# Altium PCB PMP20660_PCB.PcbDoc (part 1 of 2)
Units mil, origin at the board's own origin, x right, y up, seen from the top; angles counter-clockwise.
Board outline 3850 x 3650 mil, 6 copper layers (Top Layer, MidLayer1, MidLayer2, MidLayer3, MidLayer4, Bottom Layer), stack 61.3 mil thick; 110 components, 43 nets, 1166 pads, 406 vias.
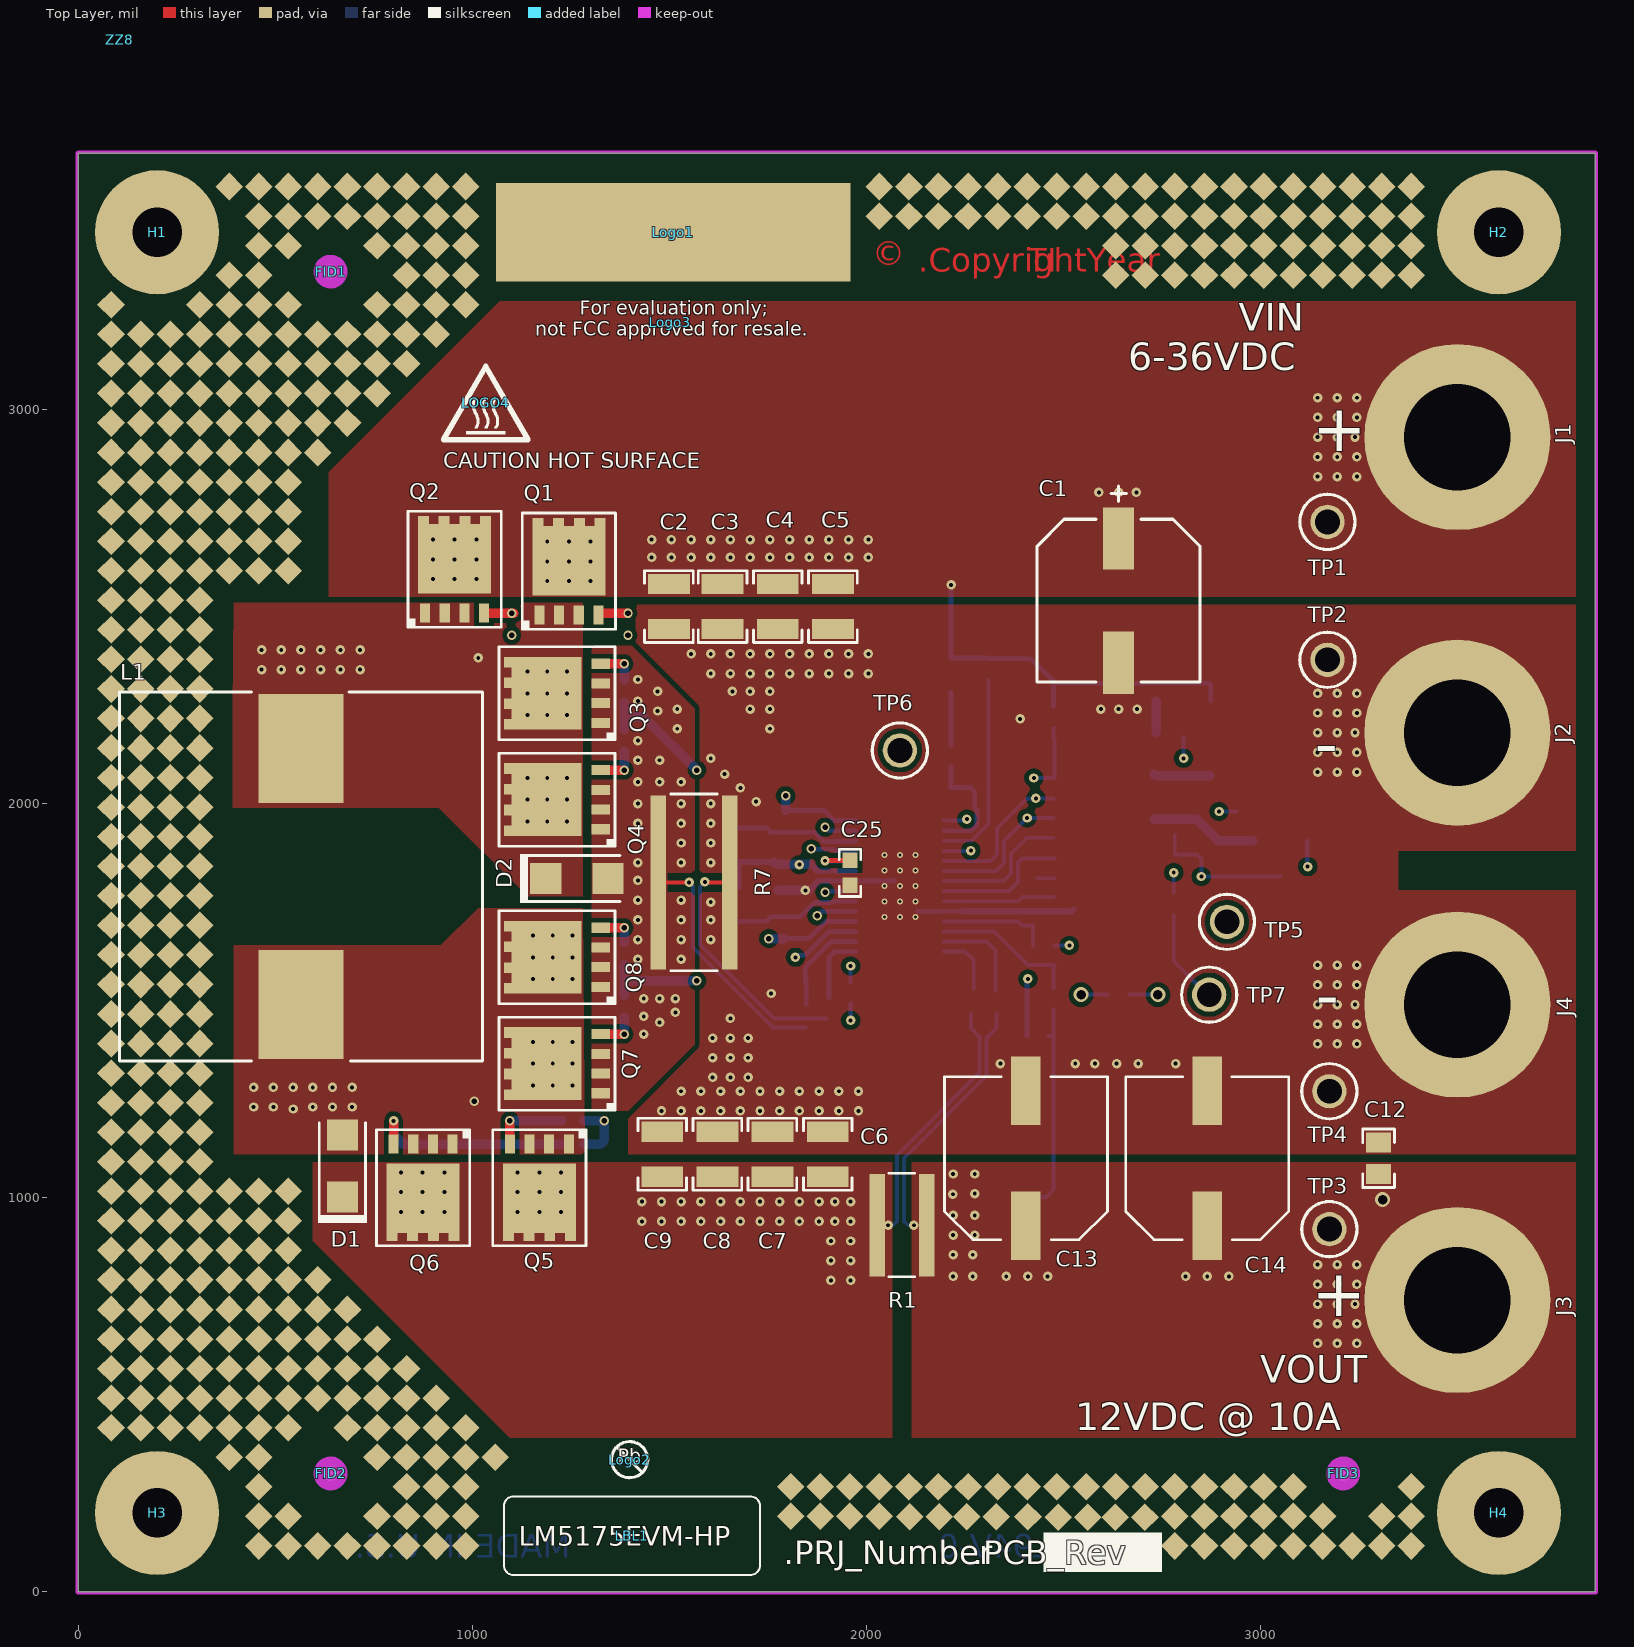
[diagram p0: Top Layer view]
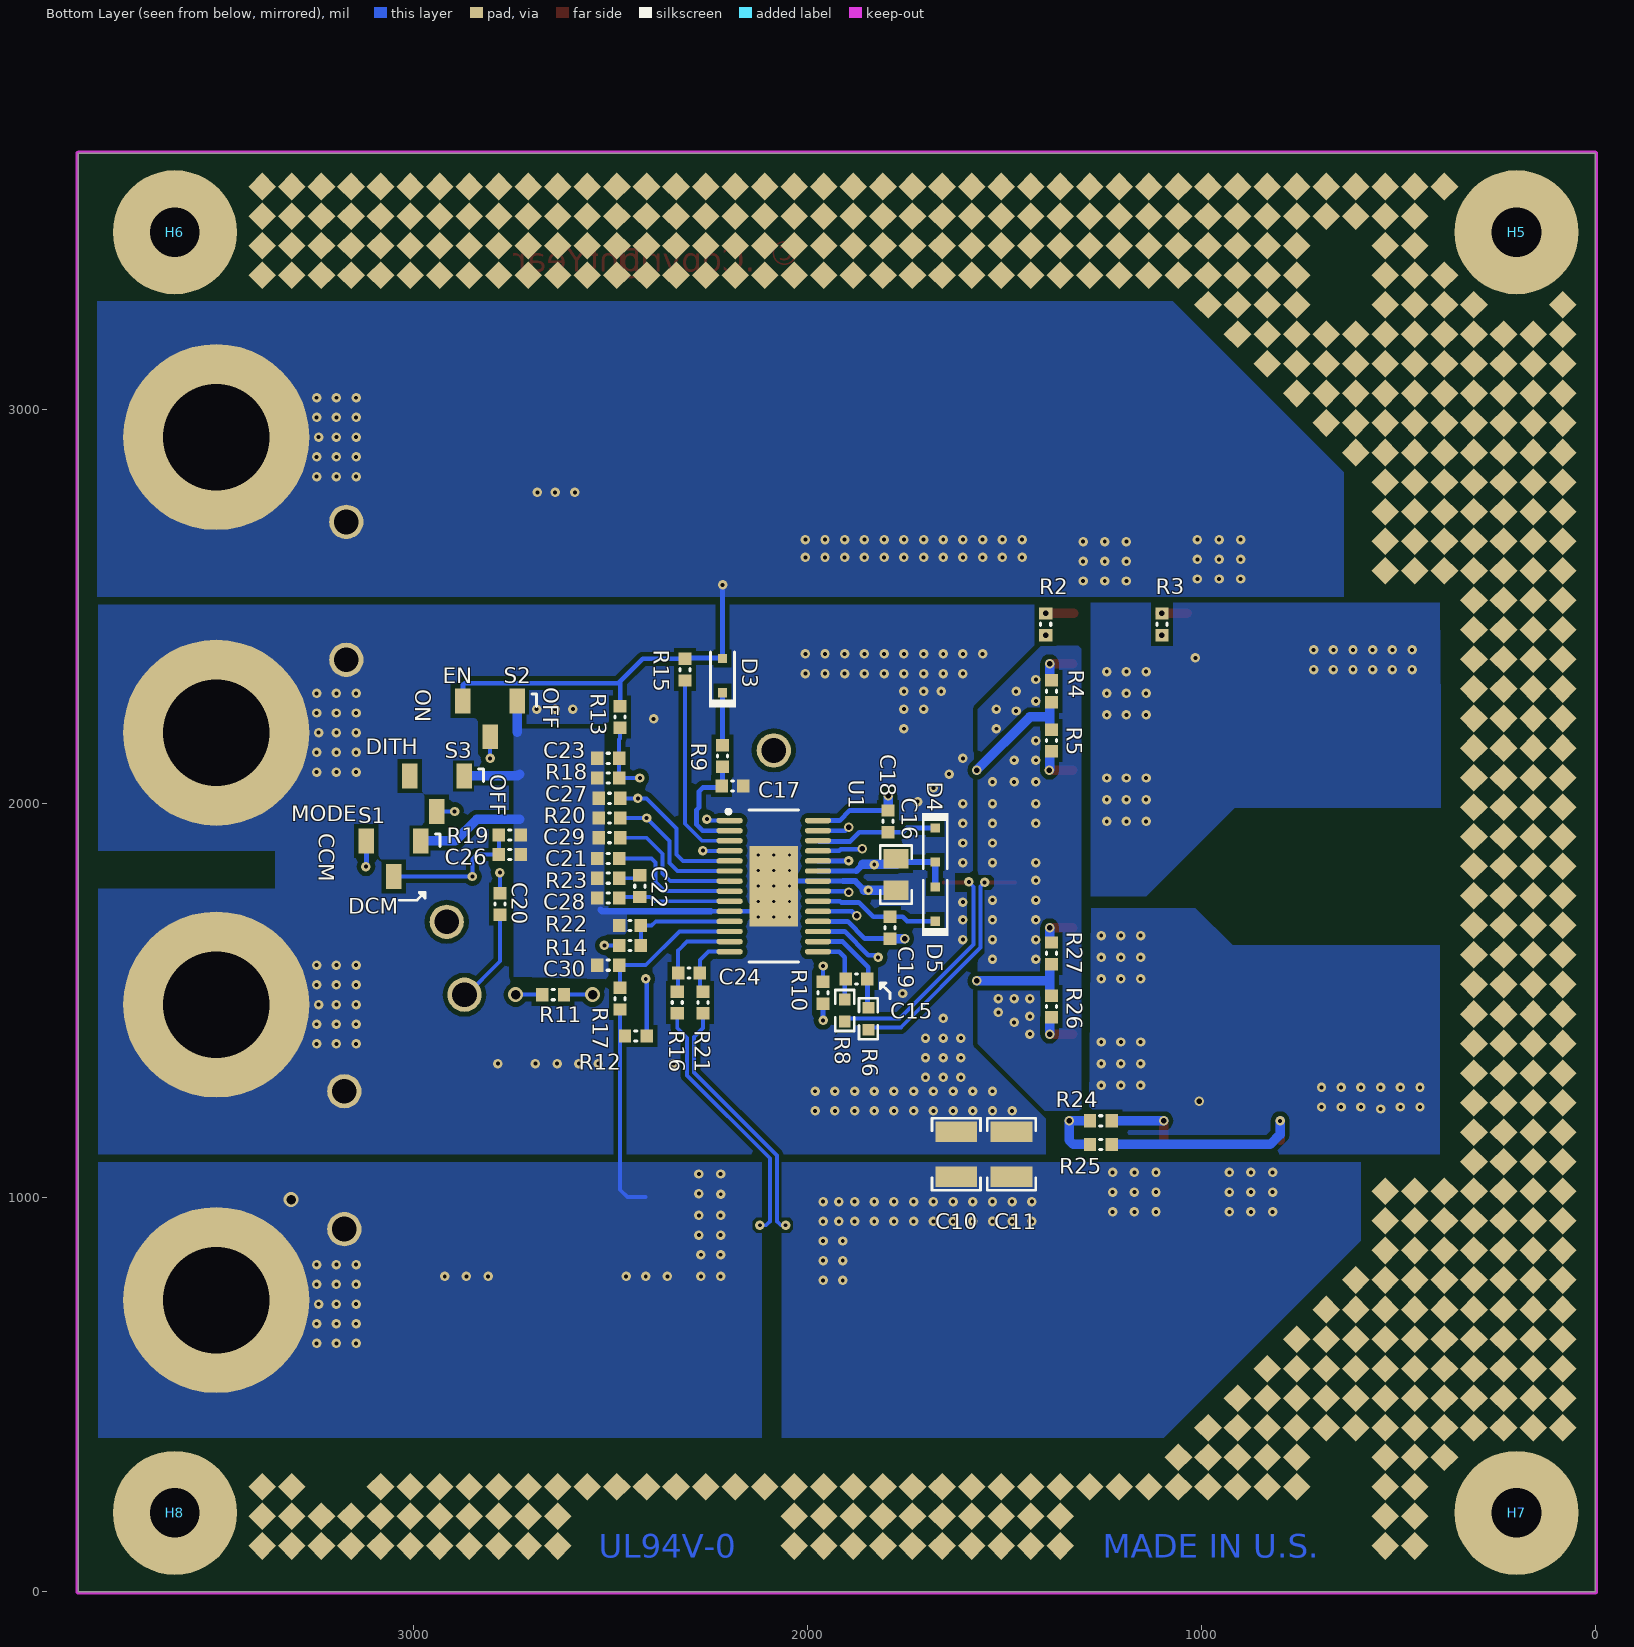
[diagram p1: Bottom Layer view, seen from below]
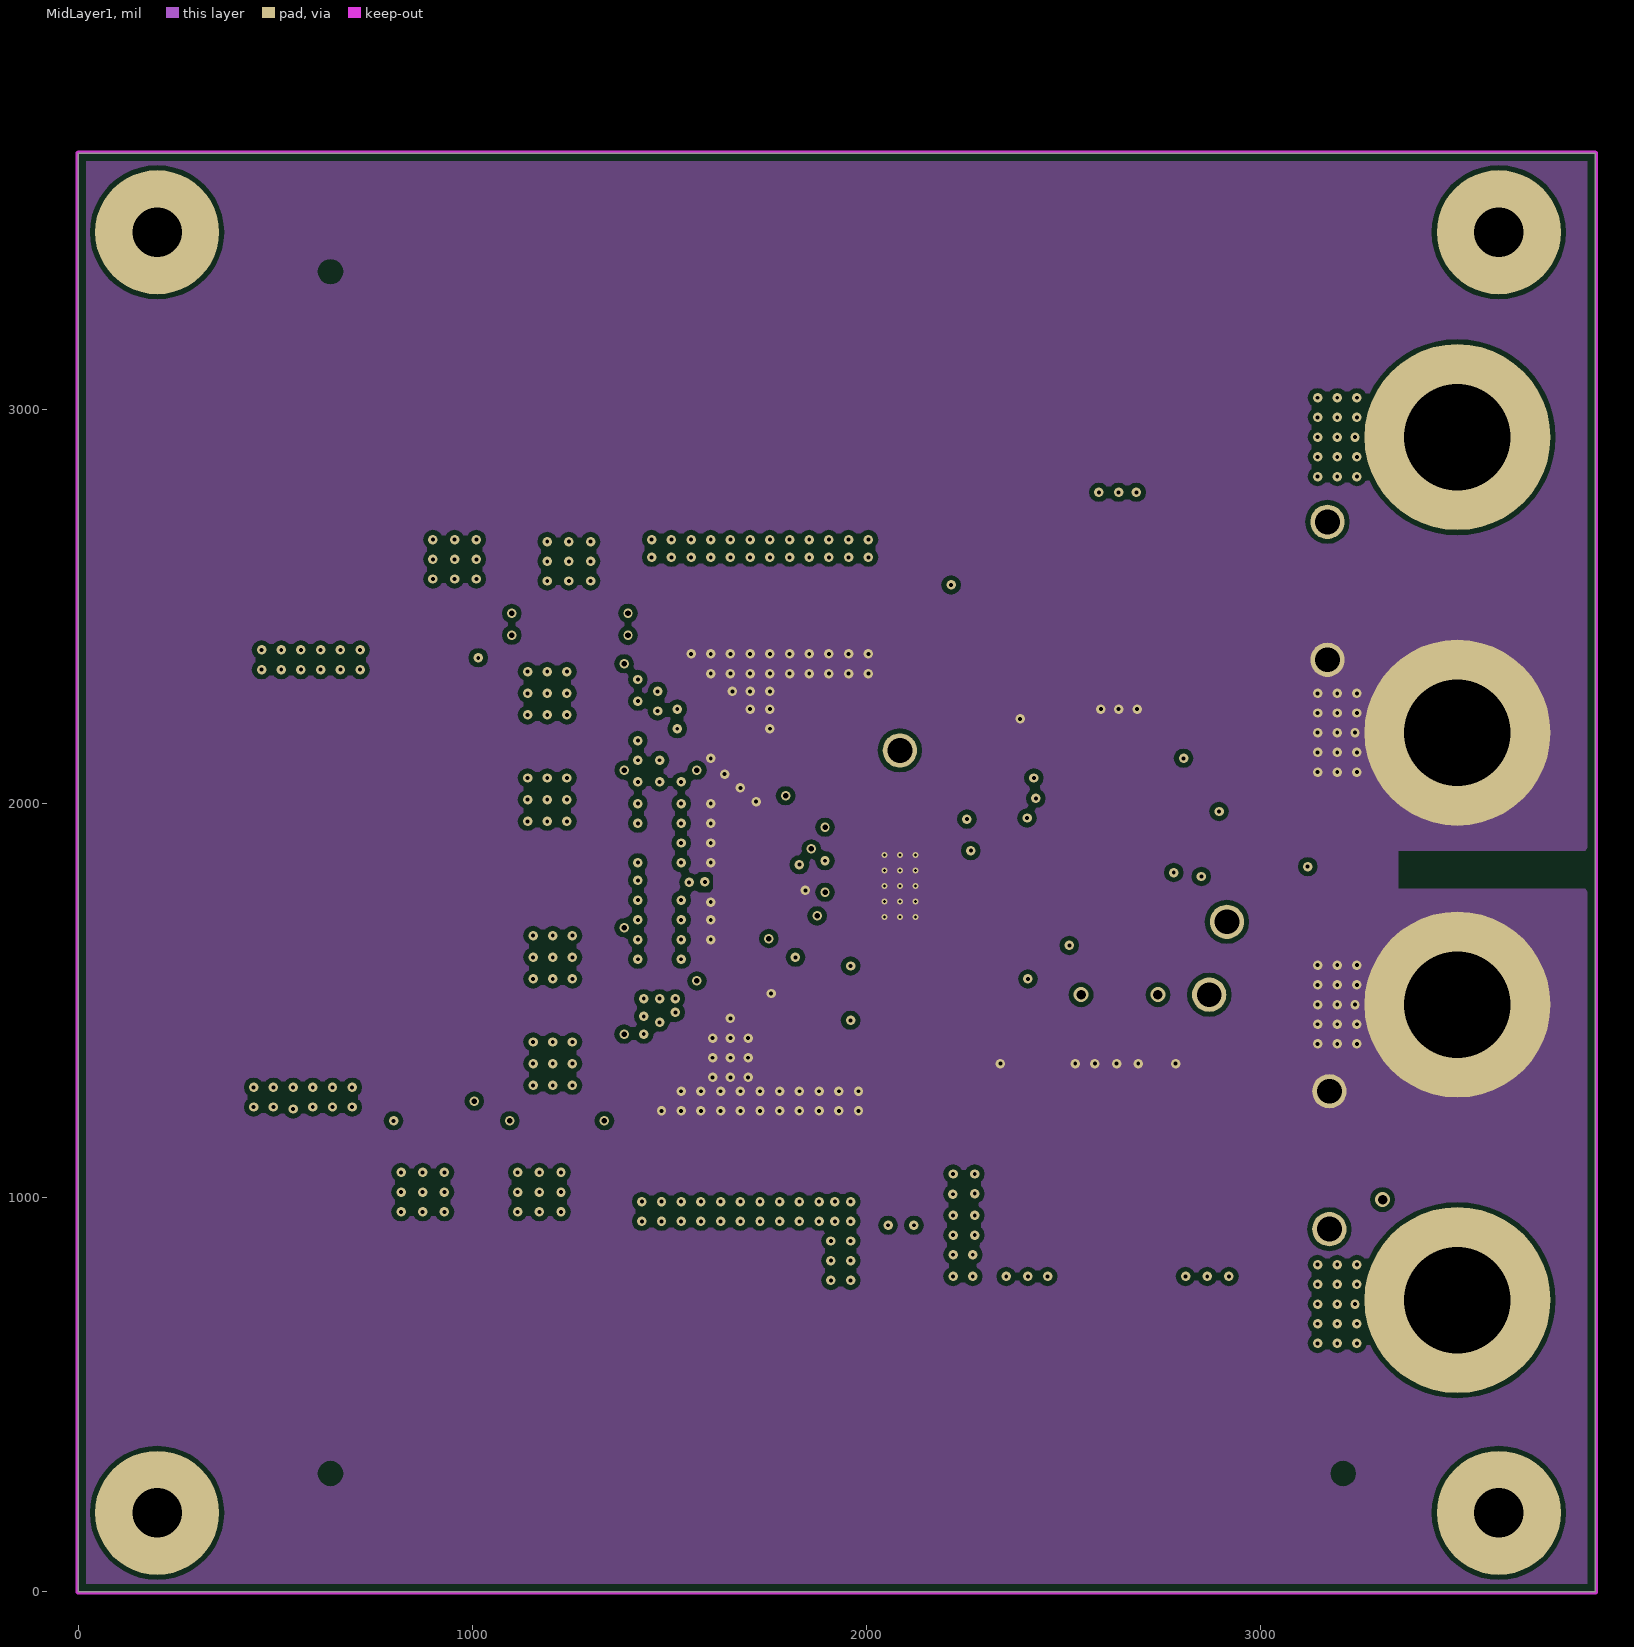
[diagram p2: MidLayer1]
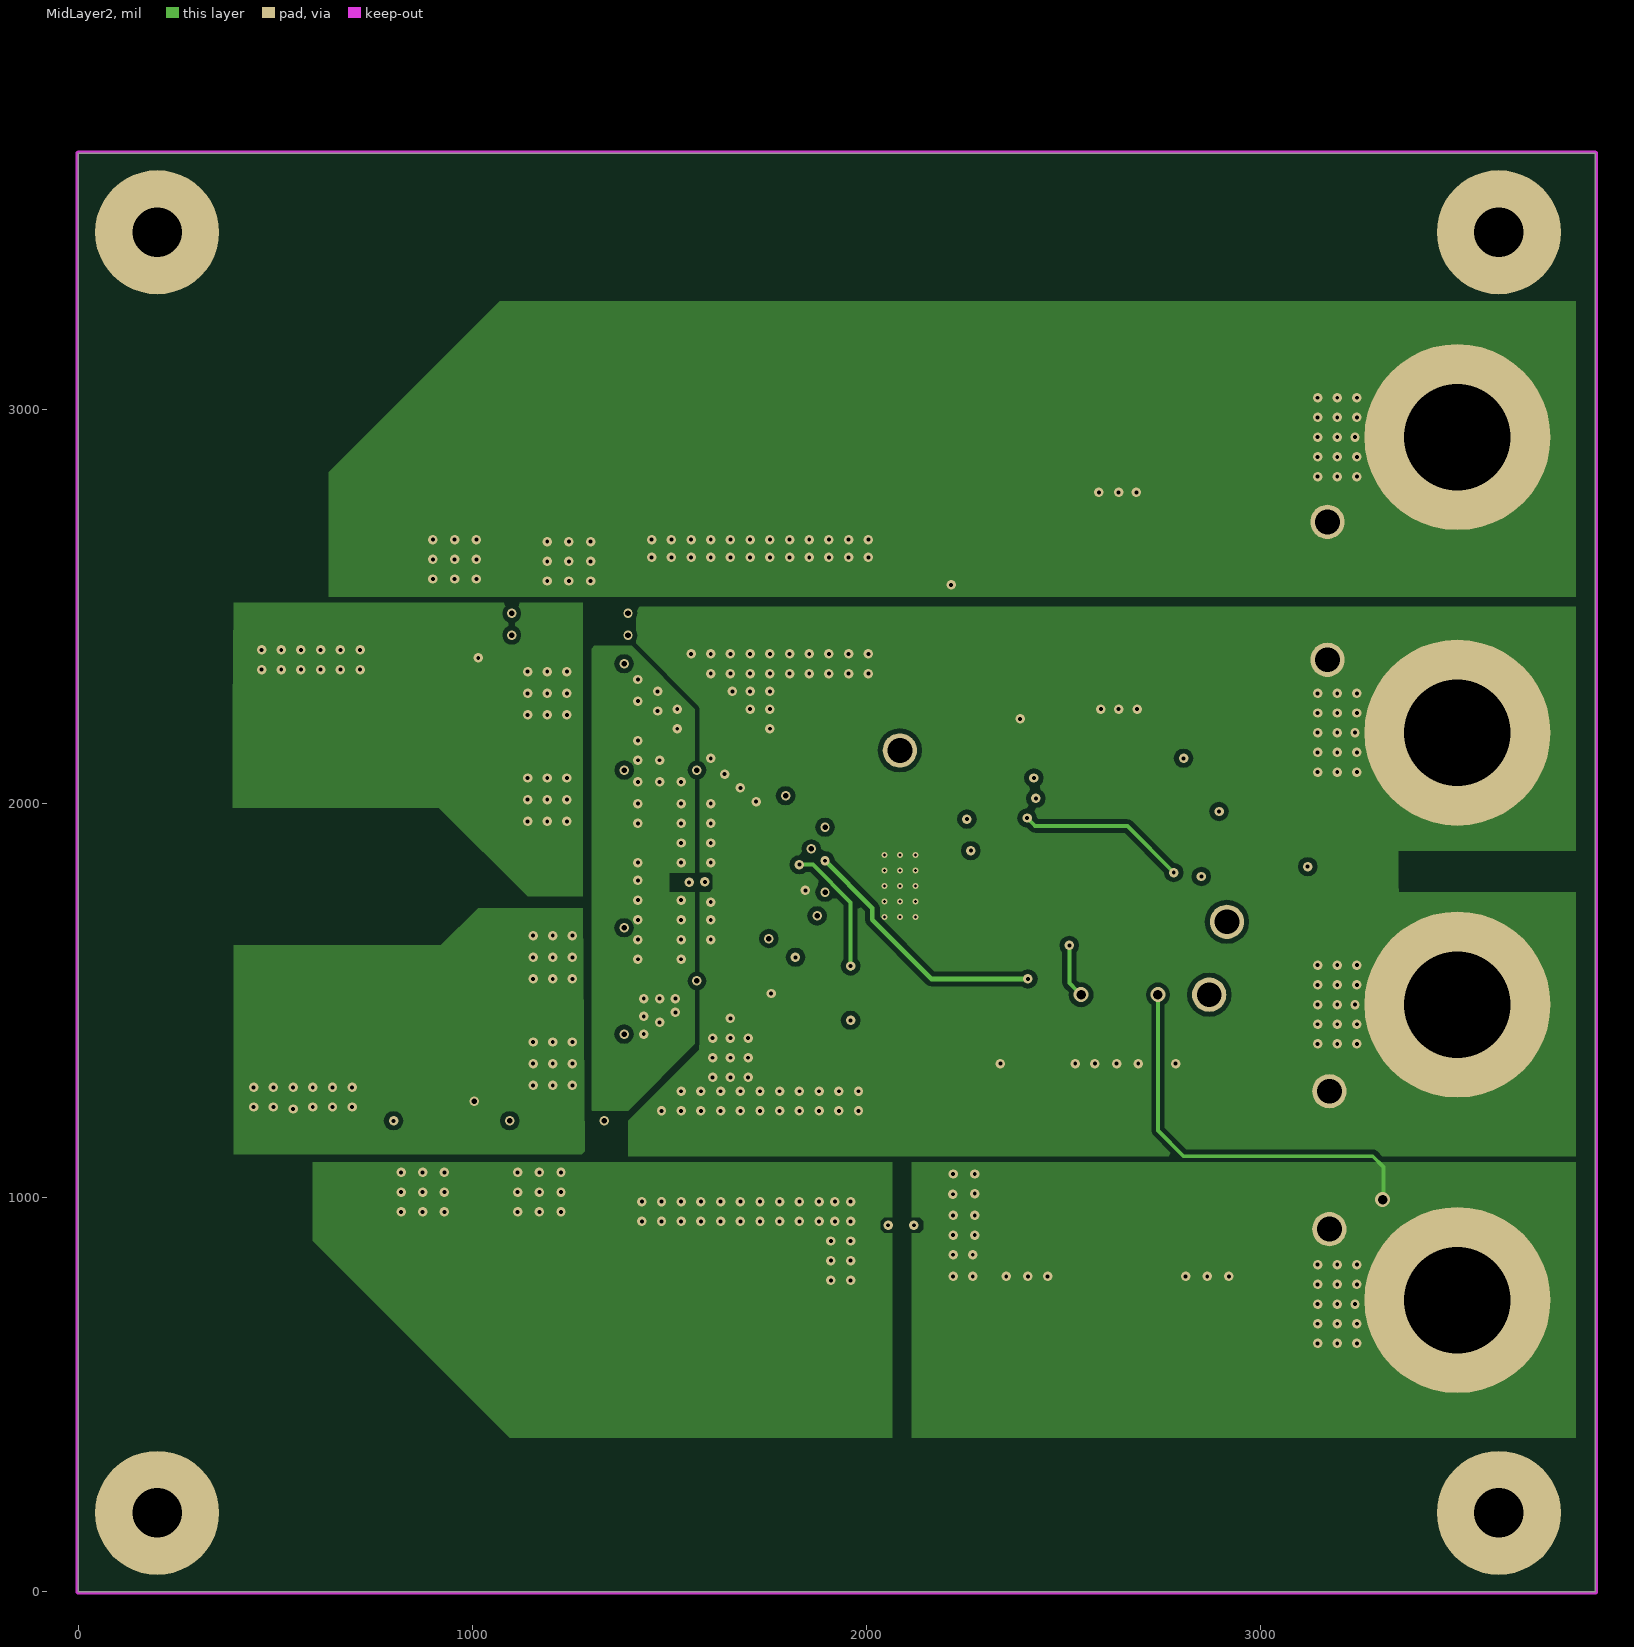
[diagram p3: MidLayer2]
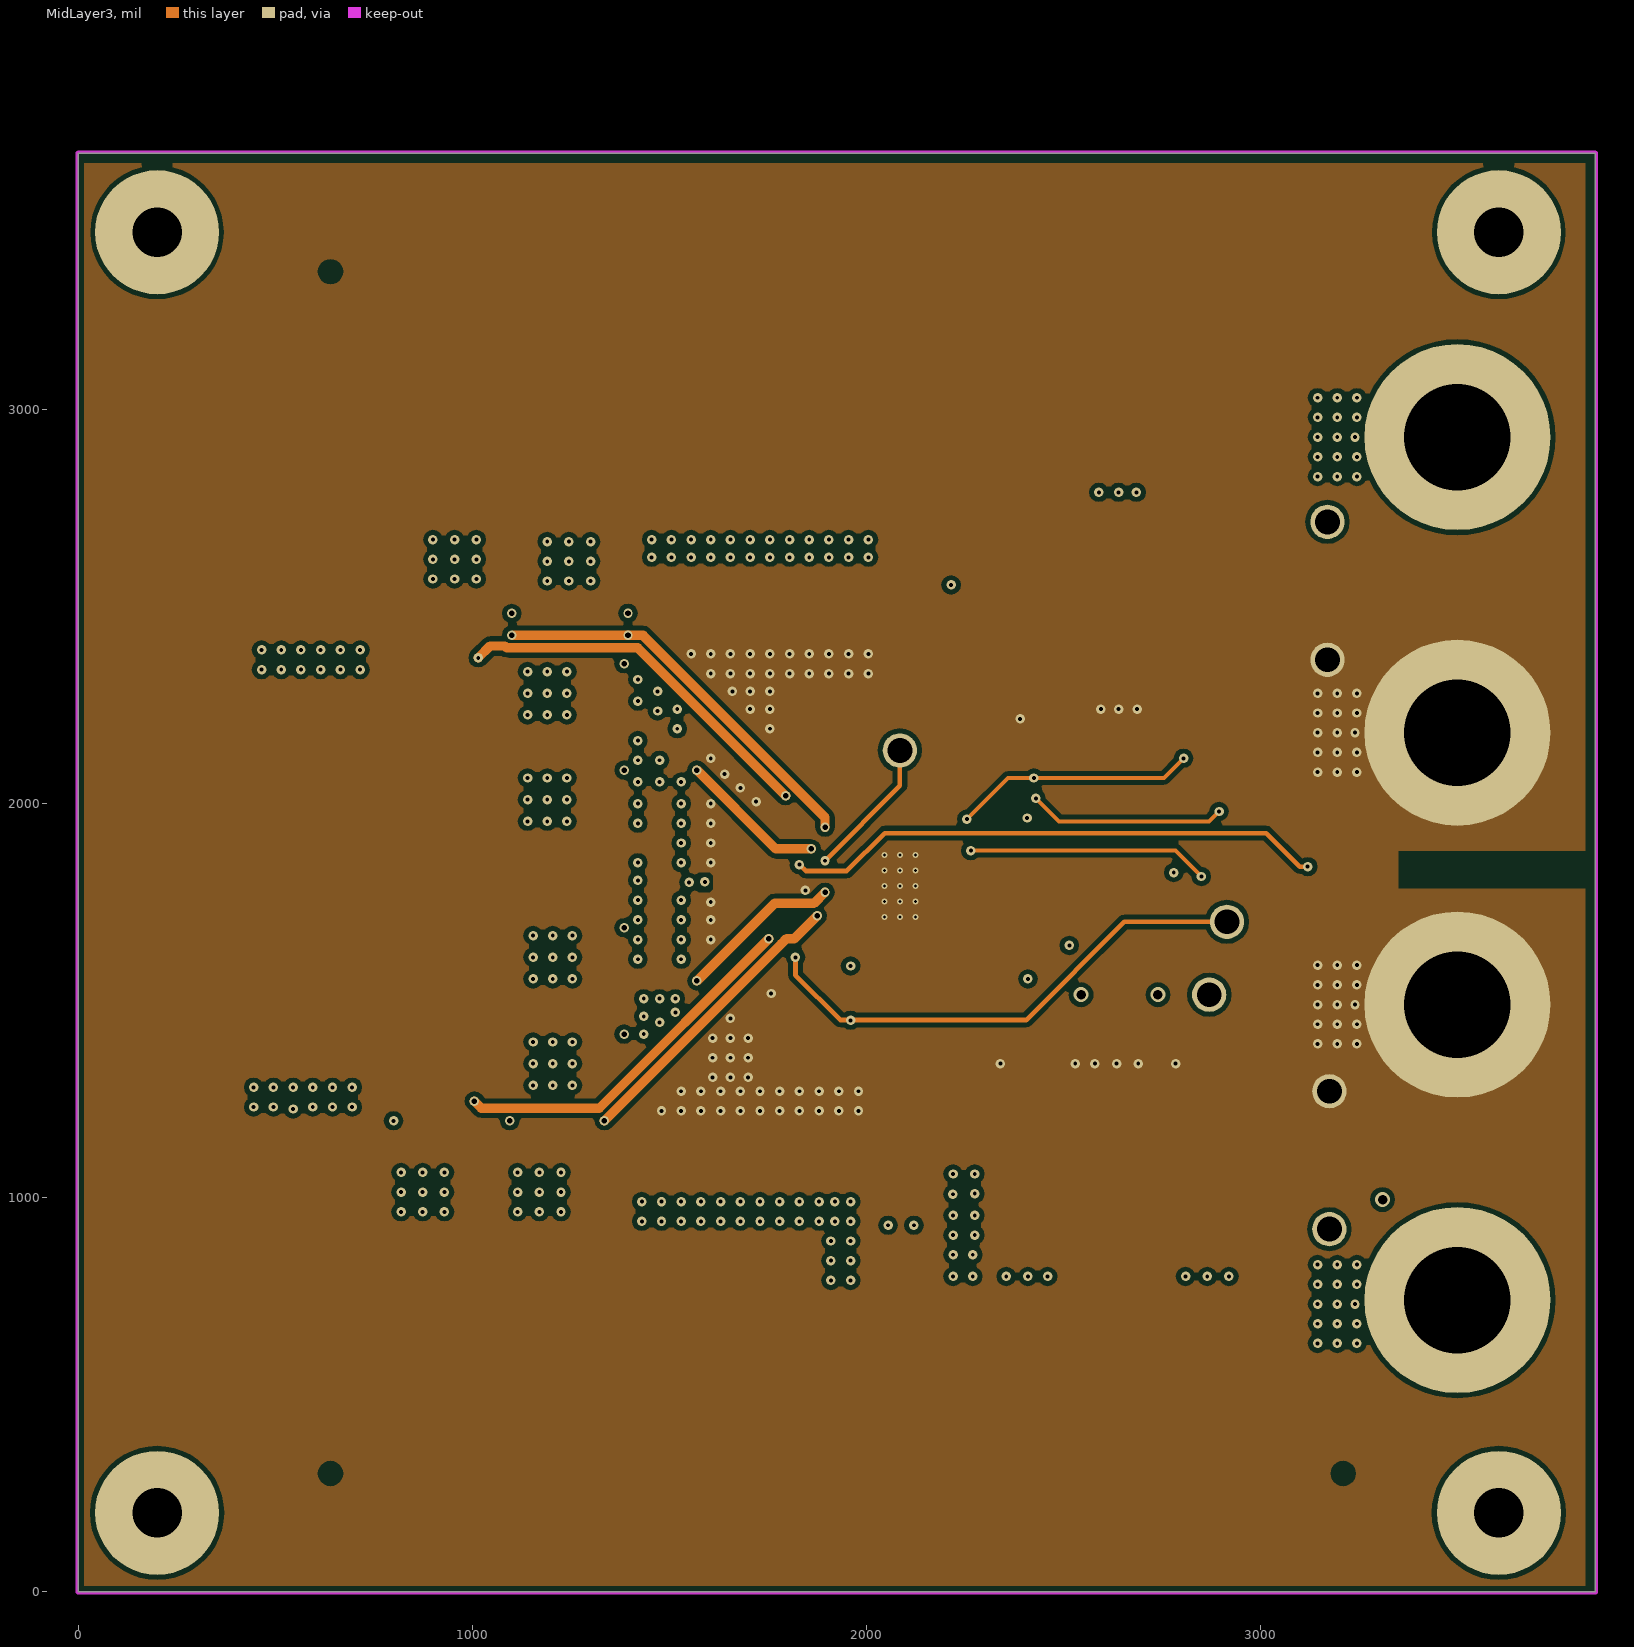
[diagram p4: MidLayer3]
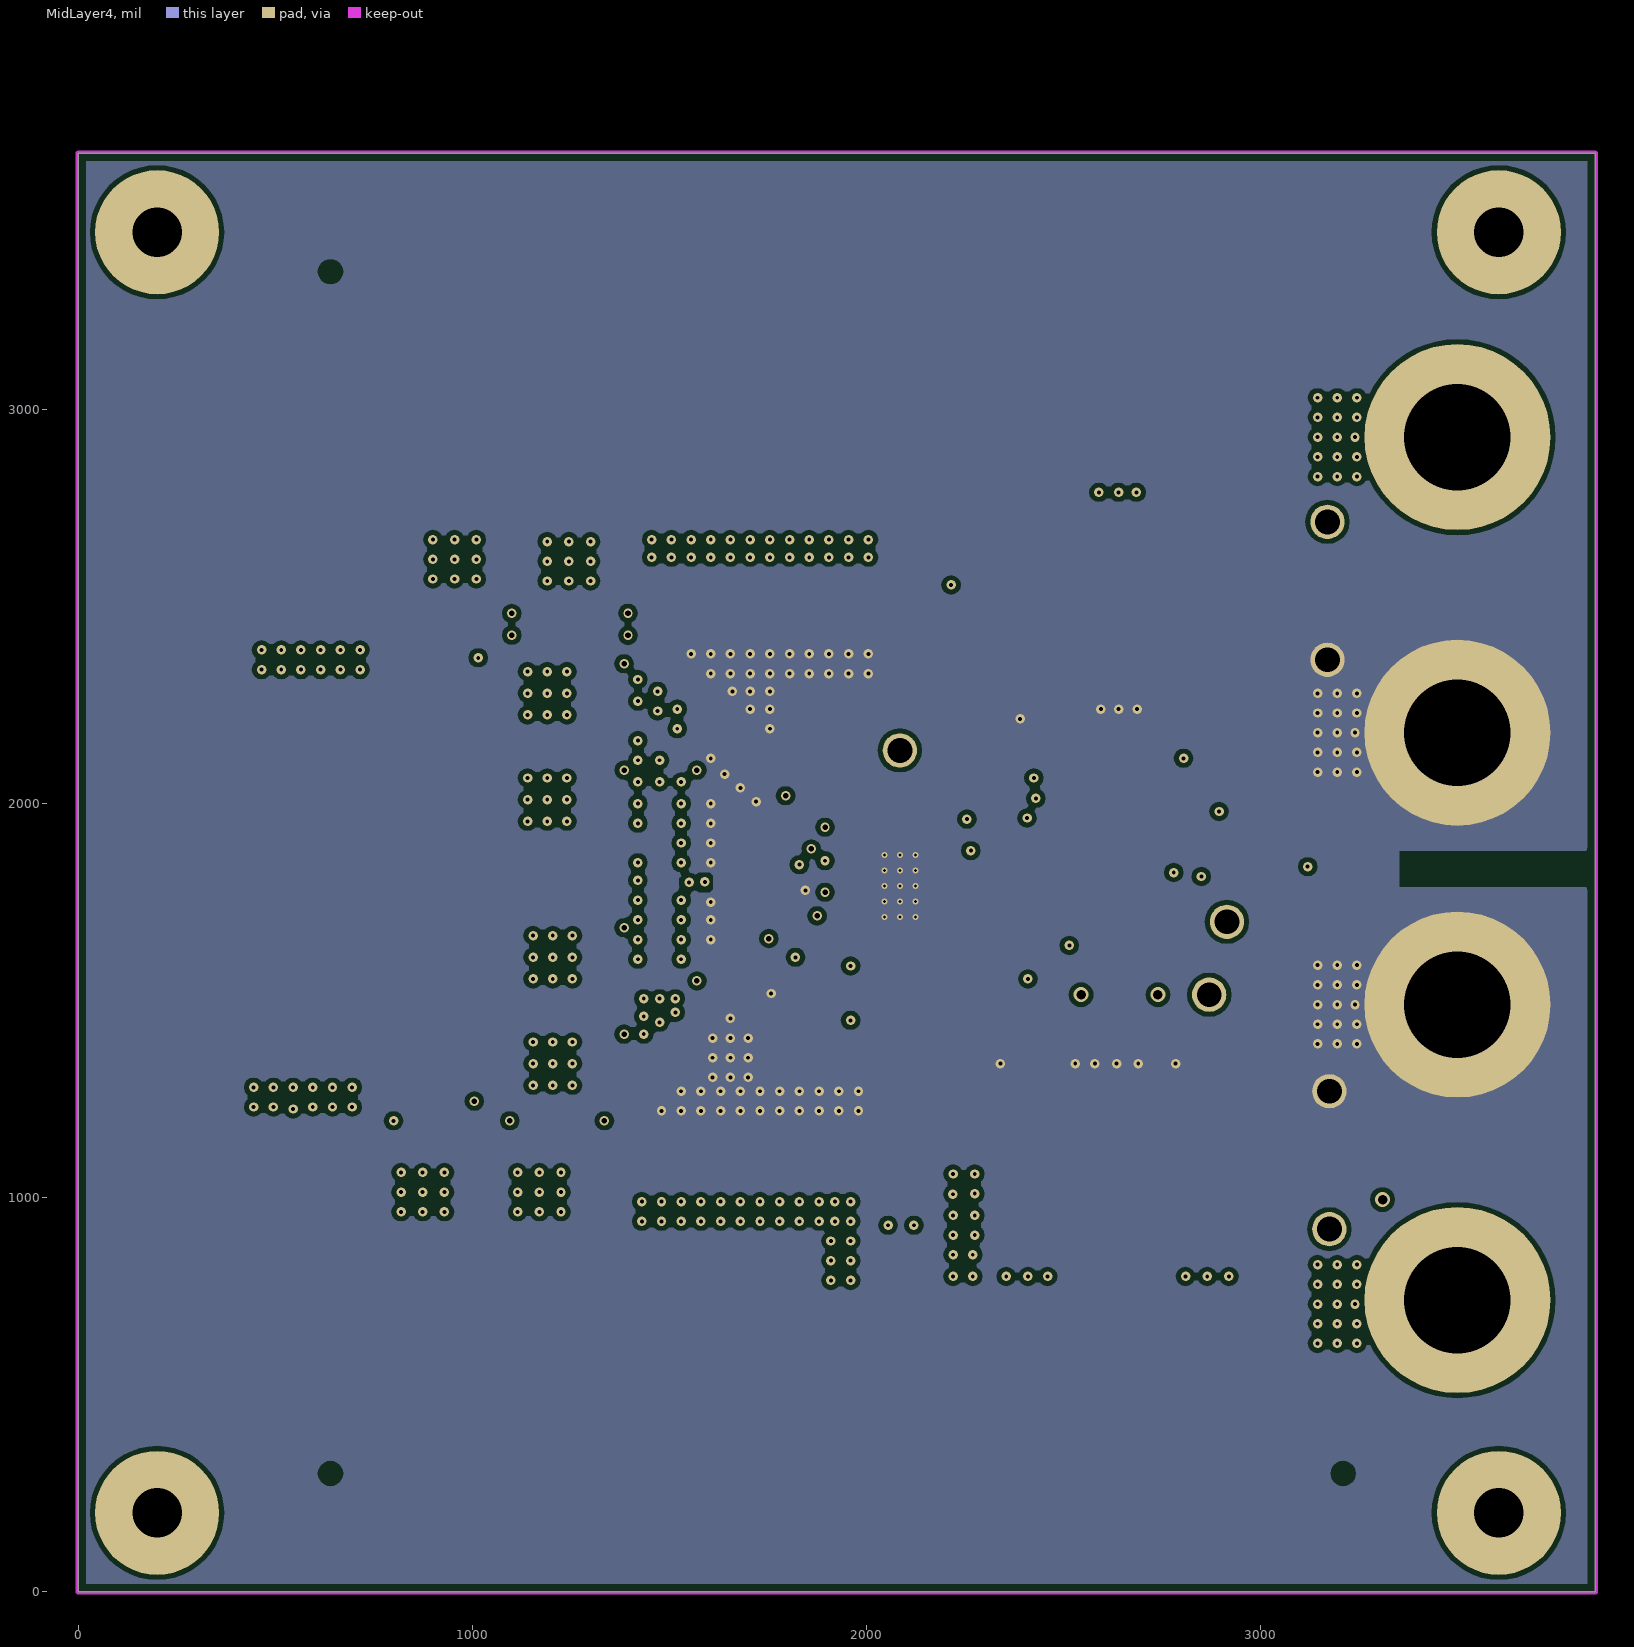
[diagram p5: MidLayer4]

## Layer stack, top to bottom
Top Solder: solder mask 0.4, Solder Resist, Dk 3.5
Top Layer: signal copper 2.8
Dielectric1: prepreg 8.9, FR-4, Dk 4.2
MidLayer1: signal copper 2.8
Dielectric2: prepreg 8.9, FR-4, Dk 4.8
MidLayer2: signal copper 2.8
Dielectric3: prepreg 8.9, FR-4, Dk 4.2
MidLayer3: signal copper 2.8
Dielectric4: prepreg 8.9, FR-4, Dk 4.8
MidLayer4: signal copper 2.8
Dielectric5: core 8.9, FR-4, Dk 4.8
Bottom Layer: signal copper 2.8
Bottom Solder: solder mask 0.4, Solder Resist, Dk 3.5

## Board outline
0,0 3850,0 3850,3650 0,3650

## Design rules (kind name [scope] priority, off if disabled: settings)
AcuteAngle [All] p1: minimum=4.50000000000000E+0001 checktracksonly=FALSE
AssemblyTestPointUsage [All] p1: valid=2
Clearance Clearance_BoardEdge_MountingHoles [OnCopper and InComponentClass('Mounting Holes') vs KeepOut] p1: gap=40 ignorepadtopadclearanceinfootprint=FALSE except(0: Arc-Hole Track-Hole SMDPad-Hole THPad-Hole Via-Hole Fill-Hole Poly-Hole Region-Hole Text-Hole)
Clearance Clearance_BoardEdge_Poly [OnCopper and InPoly vs KeepOut] p2: gap=25 ignorepadtopadclearanceinfootprint=FALSE except(0: Arc-Hole Track-Hole SMDPad-Hole THPad-Hole Via-Hole Fill-Hole Poly-Hole Region-Hole Text-Hole)
Clearance Clearance_BoardEdge [OnCopper and Not InComponentClass('Logo') and not InComponentClass('FiducialMark') and not InRegion(1000,500,4000,800) and Not IsKeepout vs KeepOut] p3: gap=47 ignorepadtopadclearanceinfootprint=FALSE except(0: Arc-Hole Track-Hole SMDPad-Hole THPad-Hole Via-Hole Fill-Hole Poly-Hole Region-Hole Text-Hole)
Clearance Clearance_Poly [InPolygon] p4: gap=12 ignorepadtopadclearanceinfootprint=FALSE except(0: Arc-Hole Track-Hole SMDPad-Hole THPad-Hole Via-Hole Fill-Hole Poly-Hole Region-Hole Text-Hole)
Clearance [All] p5: gap=7.87 ignorepadtopadclearanceinfootprint=FALSE except(0: Arc-Hole Track-Hole SMDPad-Hole THPad-Hole Via-Hole Fill-Hole Poly-Hole Region-Hole Text-Hole)
ComponentClearance ComponentClearance_Shunt [InComponentClass('Header') vs InComponentClass('Shunt')] p1: gap=0 collisioncheckmode=3 verticalgap=0 showdistances=FALSE
ComponentClearance ComponentClearance_MountingHoles_FiducialMarks [InComponentClass('Mounting Holes') vs InComponentClass('FiducialMark')] p2: gap=42 collisioncheckmode=3 verticalgap=10 showdistances=FALSE
ComponentClearance ComponentClearance_Logo [InComponentClass('Logo')] p3: gap=50 collisioncheckmode=3 verticalgap=10 showdistances=FALSE
ComponentClearance ComponentClearance_ScrewToNut [(HasFootprint('NY PMS 440 0025 PH')) vs (HasFootprint('Keystone_1902C'))] p4: gap=5 collisioncheckmode=3 verticalgap=10 showdistances=FALSE
ComponentClearance ComponentClearance_MountingHoles [InComponentClass('Mounting Holes')] p5: gap=200 collisioncheckmode=3 verticalgap=100000 showdistances=FALSE
ComponentClearance ComponentClearance_SmallPassives [HasFootprint('0201*') or HasFootprint('0402*') or HasFootprint('0508') or HasFootprint('0603*') or HasFootprint('0612') or HasFootprint('0805*') or HasFootprint('0815*') or HasFootprint('0830*') or HasFootprint('1206*') or HasFootprint('1210*') or HasFootprint('1808*') or HasFootprint('1812*') or HasFootprint('1825*') or HasFootprint('2010*') or HasFootprint('2220*') or HasFootprint('2225*') or HasFootprint('2512*') or HasFootprint('2728*') or HasFootprint('3518*') vs HasFootprint('0201*') or HasFootprint('0402*') or HasFootprint('0508') or HasFootprint('0603*') or HasFootprint('0612') or HasFootprint('0805*') or HasFootprint('0815*') or HasFootprint('0830*') or HasFootprint('1206*') or HasFootprint('1210*') or HasFootprint('1808*') or HasFootprint('1812*') or HasFootprint('1825*') or HasFootprint('2010*') or HasFootprint('2220*') or HasFootprint('2225*') or HasFootprint('2512*') or HasFootprint('2728*') or HasFootprint('3518*')] p6: gap=10 collisioncheckmode=3 verticalgap=10 showdistances=FALSE
ComponentClearance ComponentClearance_THtoSMT [IsThruComponent vs IsSMTComponent] p7: gap=40 collisioncheckmode=3 verticalgap=30 showdistances=FALSE
ComponentClearance ComponentClearance_THtoTH [IsThruComponent vs IsThruComponent] p8: gap=25 collisioncheckmode=3 verticalgap=15 showdistances=FALSE
ComponentClearance [All] p9: gap=40 collisioncheckmode=3 verticalgap=10 showdistances=FALSE
DiffPairsRouting [All] p1: maxlimit=100 minlimit=10 mostfreqgap=10 toplayer_minwidth=15 toplayer_maxwidth=15 toplayer_prefwidth=15 midlayer1_minwidth=15 midlayer1_maxwidth=15 midlayer1_prefwidth=15 midlayer2_minwidth=15 midlayer2_maxwidth=15 midlayer2_prefwidth=15 midlayer3_minwidth=15 midlayer3_maxwidth=15 midlayer3_prefwidth=15 midlayer4_minwidth=15 midlayer4_maxwidth=15 midlayer4_prefwidth=15 bottomlayer_minwidth=15 bottomlayer_maxwidth=15 bottomlayer_prefwidth=15 maxuncoupledlength=1000
FabricationTestPointUsage TestPointUsage [All] p1: valid=2 allowmultiple=FALSE
FabricationTestpoint Testpoint [All] p1: side=3 testpointundercomponent=TRUE minsize=40 maxsize=100 preferedsize=60 minholesize=0 maxholesize=40 preferedholesize=32 testpointgrid=1 allowsidetop=TRUE allowsidebottom=TRUE usegrid=TRUE gridtolerance=0.01
FanoutControl Fanout_LCC [IsLCC] p1: bgadir=Out bgaviamode=Centered fanoutstyle=Auto fanoutdirection=Alternating viagrid=1 // Fanout_LCC (Default Rule)
FanoutControl Fanout_BGA [IsBGA] p2: bgadir=Out bgaviamode=Centered fanoutstyle=Auto fanoutdirection=Alternating viagrid=1 // Fanout_BGA (Default Rule)
FanoutControl Fanout_Default [All] p4: bgadir=Out bgaviamode=Centered fanoutstyle=Auto fanoutdirection=Alternating viagrid=1 // Fanout_Default (Default Rule)
FanoutControl Fanout_Small [(CompPinCount < 5)] p5: bgadir=Out bgaviamode=Centered fanoutstyle=Auto fanoutdirection=OutThenIn viagrid=1 // Fanout_Small (Default Rule)
HoleSize [All] p1: absolutevalues=TRUE maxlimit=280 minlimit=7.87 maxpercent=80.000 minpercent=20.000
MinimumAnnularRing MinimumAnnularRing_ThermalPadVias [IsVia and InAnyComponent] p1: minimumring=3.94
MinimumAnnularRing [All] p2: minimumring=5
MinimumSolderMaskSliver MinimumSolderMaskSliver_Logo [InComponentClass('Logo') vs InComponentClass('Logo')] p1: minsoldermaskwidth=0.7
MinimumSolderMaskSliver [All] p2: minsoldermaskwidth=3.94
PlaneConnect [All] p1: planeconnectstyle=Relief reliefexpansion=10 reliefentries=4 reliefconductorwidth=10 reliefairgap=10
PolygonConnect [All] p1: connectstyle=Direct reliefconductorwidth=10 reliefentries=4 polygonreliefangle="90 Angle" airgapwidth=10
RoutingVias ThermalPadVias [IsVia and InAnyComponent] p1: holewidth=7.87 width=19.68 viastyle="Through Hole" minholewidth=7.87 minwidth=15.75 maxholewidth=12.99 maxwidth=23.62
RoutingVias [All] p2: holewidth=10 width=24 viastyle="Through Hole" minholewidth=7.87 minwidth=13.78 maxholewidth=40 maxwidth=65
SMDToCorner [All] p1: distance=30000
SilkToBoardRegionClearance [NOT ((IsComment OR IsDesignator) AND (Hide <> 'FAIL')) AND NOT InRegion (100,500,4000,800)] p1:
SilkToSilkClearance [All] p1: silktosilkclearance=5
SilkToSolderMaskClearance SilkscreenOverComponentPads [IsPad] p1: minsilkscreentomaskgap=5 clearancetoexposedcopper=TRUE
SolderMaskExpansion [All] p1: expansion=1.97
Width [All] p1: maxlimit=100 minlimit=6 preferedwidth=10 checkconnectedcopper=TRUE
15 further rules are at their usual default settings.

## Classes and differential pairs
component class SV601157A: C1 C2 C3 C4 C5 C6 C7 C8 C9 C10 C11 C12 C13 C14 C15 C16 C17 C18 C19 C20 C21 C22 C23 C24 C25 C26 C27 C28 C29 C30 D1 D2 D3 D4 D5 J1 J2 J3 J4 L1 Q1 Q2 Q3 Q4 Q5 Q6 Q7 Q8 R1 R2 R3 R4 R5 R6 R7 R8 R9 R10 R11 R12 R13 R14 R15 R16 R17 R18 R19 R20 R21 R22 R23 R24 R25 R26 R27 S1 S2 S3 TP1 TP2 TP3 TP4 TP5 TP6 TP7 U1
component class Label: LBL1
component class AssemblyNote: ZZ1 ZZ2 ZZ3 ZZ4 ZZ5 ZZ6 ZZ7 ZZ8
component class FiducialMark: FID1 FID2 FID3
component class SV601157A-HW: FID1 FID2 FID3 H1 H2 H3 H4 H5 H6 H7 H8 LBL1 Logo1 Logo2 Logo3 LOGO4 ZZ1 ZZ2 ZZ3 ZZ4 ZZ5 ZZ6 ZZ7 ZZ8
component class Logo: Logo1
component class "Mounting Holes": H1 H2 H3 H4

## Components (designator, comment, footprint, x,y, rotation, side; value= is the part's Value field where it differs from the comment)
C1 "PCR1H181MCL1GS" CR_1000x1270 2640,2515 r270 top
C2 "GRM32ER71H106KA12L" 1210 1498.7,2500 r270 top
C3 "GRM32ER71H106KA12L" 1210 1635,2500 r270 top
C4 "GRM32ER71H106KA12L" 1210 1775,2500 r270 top
C5 "GRM32ER71H106KA12L" 1210 1915,2500 r270 top
C6 "GRM32ER71C226ME18L" 1210 1901.85,1110 r90 top
C7 "GRM32ER71C226ME18L" 1210 1761.54,1110 r90 top
C8 "GRM32ER71C226ME18L" 1210 1621.85,1110 r90 top
C9 "GRM32ER71C226ME18L" 1210 1481.85,1110 r90 top
C10 "GRM32ER71C226ME18L" 1210 1621.85,1110 r90 bottom
C11 "GRM32ER71C226ME18L" 1210 1481.85,1110 r90 bottom
C12 "GRM219R71E105KA88D" 0805_HV 3300,1100 r90 top
C13 "16SVP330M" SM_RADIAL_10AMM 2405,1100 r90 top
C14 "16SVP330M" SM_RADIAL_10AMM 2865,1100 r90 top
C15 "GRM1885C1H470JA01D" 0603L 1875,1555 r0 bottom
C16 "GRM21BR71C475KA73L" 0805_HV 1775,1820 r90 bottom
C17 "GRM188R72A104KA35D" 0603L 2190,2045 r180 bottom
C18 "GRM188R71E224KA88D" 0603L 1795,1955 r270 bottom
C19 "GRM188R71E224KA88D" 0603L 1790,1685 r270 bottom
C20 "GRM1885C2A101JA01D" 0603L 2780,1745 r90 bottom
C21 "GRM188R72A104KA35D" 0603L 2505,1860.63 r0 bottom
C22 "C0603C223K5RACTU" 0603L 2425,1790.63 r90 bottom
C23 "47pF" 0603L 2505,2115 r0 bottom
C24 "GRM188R71C334KA01D" 0603L 2300,1570 r180 bottom
C25 "GRM188R71E224KA88D" 0603 1958.62,1824.19 r270 top
C26 "47pF" 0603L 2755,1870.63 r180 bottom
C27 "C0603C223K5RACTU" 0603L 2502.2,2013.43 r0 bottom
C28 "GRM1885C2A101JA01D" 0603L 2505,1760.63 r0 bottom
C29 "GRM1885C2A101JA01D" 0603L 2502.2,1913.43 r0 bottom
C30 "GRM1885C2A101JA01D" 0603L 2505,1590 r0 bottom
D1 "RSX501L-20TE25" SMA 670,1080 r90 top
D2 "RB050L-60TE25" SMA 1265,1810 r0 top
D3 "PMEG6010CEJ,115" SOD-323F 2215,2325 r90 bottom
D4 "BAS316,115" sod-323 1675,1895 r270 bottom
D5 "BAS316,115" sod-323 1675,1745 r90 bottom
FID1 "Fiducial" Fiducial10-20 640,3350 r0 top
FID2 "Fiducial" Fiducial10-20 640,300 r0 top
FID3 "Fiducial" Fiducial10-20 3210,300 r0 top
H1 "NY PMS 440 0025 PH" "NY PMS 440 0025 PH" 200,3450 r0 top locked
H2 "NY PMS 440 0025 PH" "NY PMS 440 0025 PH" 3605,3450 r0 top locked
H3 "NY PMS 440 0025 PH" "NY PMS 440 0025 PH" 200,200 r0 top locked
H4 "NY PMS 440 0025 PH" "NY PMS 440 0025 PH" 3605,200 r0 top locked
H5 "1902C" Keystone_1902C 200,3450 r180 bottom locked
H6 "1902C" Keystone_1902C 3605,3450 r180 bottom locked
H7 "1902C" Keystone_1902C 200,200 r180 bottom locked
H8 "1902C" Keystone_1902C 3605,200 r180 bottom locked
J1 "108-0740-001" Johnson_108-0740-001 3500,2930 r90 top
J2 "108-0740-001" Johnson_108-0740-001 3500,2180 r90 top
J3 "108-0740-001" Johnson_108-0740-001 3500,740 r90 top
J4 "108-0740-001" Johnson_108-0740-001 3500,1490 r90 top
L1 "6.8µH" IND_WE-HCI_2212 565,1815 r270 top
LBL1 "LM5175EVM-HP" Label_650x200 1405,142 r0 top
Logo1 "Texas Instruments" TI_Stacked_SolderMask_Small 1510,3450 r0 top
Logo2 "Pb-Free Symbol" Pb-Free_Overlay_Small 1399,335 r0 top
Logo3 "FCC disclaimer" FCC_disclaimer_stacked 1502,3222 r0 top
LOGO4 "CAUTION HOT SURFACE" IEC_HotSurface_Small 1034,3017 r0 top
Q1 "BSC028N06NS" PG-TDSON-8 1245,2590 r90 top
Q2 "BSC028N06NS" PG-TDSON-8 955,2595 r90 top
Q3 "BSC028N06NS" PG-TDSON-8 1215,2280 r180 top
Q4 "BSC028N06NS" PG-TDSON-8 1215,2010 r180 top
Q5 "BSC014NE2LSI" PG-TDSON-8 1170,1025 r270 top
Q6 "BSC014NE2LSI" PG-TDSON-8 875,1025 r270 top
Q7 "BSC014NE2LSI" PG-TDSON-8 1215,1340 r180 top
Q8 "BSC014NE2LSI" PG-TDSON-8 1215,1610 r180 top
R1 "0.004" 2512_WIDE 2090,930 r0 top
R2 "RC0603JR-070RL" 0603L 1395,2455 r270 bottom
R3 "RC0603JR-070RL" 0603L 1100,2455 r270 bottom
R4 "RC0603JR-070RL" 0603L 1380,2285 r270 bottom
R5 "RC0603JR-070RL" 0603L 1380,2160 r90 bottom
R6 "RC0603FR-07100RL" 0603_HV 1845,1454 r270 bottom
R7 "KRL11050-C-R004-F-T1" 4320 1562.7,1800 r180 top
R8 "RC0603FR-07100RL" 0603_HV 1905,1475 r270 bottom
R9 "RC0603FR-0710RL" 0603L 2215,2120.63 r90 bottom
R10 "RC0603FR-0710KL" 0603L 1960,1520 r90 bottom
R11 "RC0603FR-0710RL" 0603L 2645,1515 r180 bottom
R12 "RC0603JR-070RL" 0603L 2435,1410 r180 bottom
R13 "RC0603FR-07249KL" 0603L 2475,2220 r90 bottom
R14 "RC0603FR-07280KL" 0603L 2450,1640 r0 bottom
R15 "RC0603JR-070RL" 0603L 2310,2340 r90 bottom
R16 "100" 0603L 2330,1495 r270 bottom
R17 "RC0603JR-070RL" 0603L 2475,1505 r90 bottom
R18 "RC0603FR-0759KL" 0603L 2505,2065 r180 bottom
R19 "RC0603FR-0793K1L" 0603L 2755,1920.63 r0 bottom
R20 "RC0603FR-07100KL" 0603L 2502.2,1963.43 r180 bottom
R21 "100" 0603L 2265,1495 r270 bottom
R22 "RC0603FR-0720KL" 0603L 2449.94,1690.63 r180 bottom
R23 "RC0603FR-0710KL" 0603L 2505,1810.63 r180 bottom
R24 "RC0603JR-070RL" 0603L 1255,1195 r0 bottom
R25 "RC0603JR-070RL" 0603L 1255,1135 r0 bottom
R26 "RC0603JR-070RL" 0603L 1380,1485 r90 bottom
R27 "RC0603JR-070RL" 0603L 1380,1620 r270 bottom
S1 "CJS-1201TA" SW_CJS_1201A 3050,1860 r0 bottom
S2 "CJS-1201TA" SW_CJS_1201A 2805,2215 r0 bottom
S3 "CJS-1201TA" SW_CJS_1201A 2940,2025 r0 bottom
TP1 "5005" Keystone5005 3170,2715 r90 top
TP2 "5006" Keystone5006 3170,2365 r90 top
TP3 "5005" Keystone5005 3175,920 r90 top
TP4 "5006" Keystone5006 3175,1270 r90 top
TP5 "5007" Keystone5007 2915,1700 r90 top
TP6 "BIAS" Keystone5007 2085,2135 r90 top
TP7 "SYNC" Keystone5007 2870,1515 r90 top
U1 "LM5175PWPR" PWP0028F_N 2085,1790.63 r180 bottom
ZZ1 "This Assembly Note is for PCB labels only" AssemblyNoteLabel 105,4553 r0 top
ZZ2 "These assemblies are ESD sensitive, ESD precautions shall be observed." AssemblyNote 105,4447.86 r0 top
ZZ3 "These assemblies must be clean and free from flux and all contaminants. Use of no clean flux is not acceptable." AssemblyNote 105,4363.05 r0 top
ZZ4 "These assemblies must comply with workmanship standards IPC-A-610 Class 2, unless otherwise specified." AssemblyNote 105,4278.24 r0 top
ZZ5 "Remove Kapton tape from switches S1 thru S3 on PCB Bottom side after final wash." AssemblyNote 105,4193.43 r0 top
ZZ6 "Set S1 switch to 'CCM' position as per silkscreen label" AssemblyNote 105,4108.62 r0 top
ZZ7 "Set S2 switch to Center position" AssemblyNote 105,4023.81 r0 top
ZZ8 "Set S3 switch to 'OFF' position per silk screen label." AssemblyNote 105,3939 r0 top

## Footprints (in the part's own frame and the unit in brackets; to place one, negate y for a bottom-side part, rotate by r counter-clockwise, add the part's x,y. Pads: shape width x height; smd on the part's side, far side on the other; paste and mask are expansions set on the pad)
0603 [mm] "0603 from SM-752 data"
  rect 1x0.95 smd: 1(-0.8,0) 2(0.8,0)
  silkscreen extent -1.52,-0.69 1.52,0.69, body extent -0.87,-0.47 0.87,0.47, height 0.85
0603_HV [mil] "Ernesto recommended land pattern.  26 mil between pads."
  rect 30x30 smd: 1(-28,0) 2(28,0)
  silkscreen extent -52,-24 52,24, body extent -34,-19 34,19, height 33
0603L [mm] "0603 from SM-752 data"
  rect 0.8x0.85 smd: 1(-0.7,0) 2(0.7,0)
  silkscreen extent -0.07,-0.33 0.07,0.33, body extent -0.87,-0.47 0.87,0.47, height 0.85
0805_HV [mil] "0805 with 30mil clearance between pads"
  rect 50x63 smd: 1(-40,0) 2(40,0)
  silkscreen extent -74,-40 74,40, body extent -43,-29 43,29, height 43
1210 [mm] "1210 from SM-752 data"
  rect 1.3x2.7 smd: 1(-1.45,0) 2(1.45,0)
  silkscreen extent -2.32,-1.57 2.32,1.57, body extent -1.7,-1.35 1.7,1.35, height 1.35
2512_WIDE [mm] "Ohmite recommended land pattern"
  rect 1x6.6 smd: 1(-1.6,0) 2(1.6,0)
  silkscreen extent -0.82,-3.32 0.82,3.35, body extent -1.65,-3.25 1.65,3.25, height 0.7
4320 [mm] "SUSUMU"
  rect 1x11.2 smd: 1(-2.3,0) 2(2.3,0)
  silkscreen extent -1.5,-5.7 1.5,5.7, body extent -2.6,-5.6 2.6,5.6, height 0.7
AssemblyNote [mil] "Assembly Note"
AssemblyNoteLabel [mil] "Assembly Note for PCB Labels"
CR_1000x1270 [mm] "SMD, 2-Leads, Dia 10.5mm, Pin Spacing 8mm"
  rect 4x2 smd: 1(-4,0) 2(4,0)
  silkscreen extent -7.4,-5.25 5.25,5.25, body extent -5.25,-5.25 5.25,5.25, height 12.71
FCC_disclaimer_stacked [mil]
Fiducial10-20 [mm]
  round 1 smd mask+0.5: 1(0,0)
  Top Layer keep-out circle w1.178: c0,0 r0.5
IEC_HotSurface_Small [mil]
  silkscreen extent -107,-93 107,92
IND_WE-HCI_2212 [mm] "WERTH ELEKTRONIK"
  rect 7x5.5 smd: 1(-8.25,0) 2(8.25,0)
  silkscreen extent -11.9,-11.7 11.9,11.7, body extent -11.75,-11.5 11.75,11.5, height 12.4
Johnson_108-0740-001 [mm] "Banana Jack Uninsulated Standard Type"
  round 12 hole 6.858: 1(0,0)
  body extent -4.77,-5.43 4.75,5.57, height 2.39
Keystone5005 [mil] "Keystone Compact loops"
  round 87 hole 63: 1(0,0)
  silkscreen extent -70,-70 70,70, body extent -63,-63 62,63, height 225
Keystone5006 [mil] "Keystone Compact loops"
  round 87 hole 63: 1(0,0)
  silkscreen extent -70,-70 70,70, body extent -63,-63 62,63, height 225
Keystone5007 [mil] "Keystone Compact loops"
  round 87 hole 63: 1(0,0)
  silkscreen extent -70,-70 70,70, body extent -63,-63 62,63, height 225
Keystone_1902C [mil] "Hex Standoff, 4-40 threaded, nylon"
  body extent -145,-126 146,126, height 501
Label_650x200 [mil] "Thermal Transfer Label"
  silkscreen extent -325,-100 325,100, body extent -325,-100 325,100, height 1
"NY PMS 440 0025 PH" [mm] "4-40 nylon screw and mounting hole"
  round 8 hole 3.2 mask+0.05: 1(0,0)
  body extent -3.3,-3.3 3.3,3.3, height 2.69
Pb-Free_Overlay_Small [mil]
  silkscreen extent -46,-46 46,46
PG-TDSON-8 [mm] "Infineon recommended land pattern"
  rect 1.2x0.65 smd: 1(-2.825,1.905) 2(-2.825,0.635) 3(-2.825,-0.635) 4(-2.825,-1.905)
  rect 0.5x0.7 smd: 5(3.175,-2) 6(3.175,-0.675) 7(3.175,0.675) 8(3.175,2)
  rect 4.5x4.7 smd paste-2.25: 9(0.675,0)
  silkscreen extent -3.74,-3 3.74,3, body extent -3.17,-2.89 3.17,2.9, height 1.1
PWP0028F_N [mm] "TSOP, 28-Leads, Body 9.7x4.4mm, Pitch 0.65mm, Exposed Pad, IPC Medium Density"
  oval 1.7x0.35 smd: 1(-2.85,4.225) 2(-2.85,3.575) 3(-2.85,2.925) 4(-2.85,2.275) 5(-2.85,1.625) 6(-2.85,0.975) 7(-2.85,0.325) 8(-2.85,-0.325) 9(-2.85,-0.975) 10(-2.85,-1.625) 11(-2.85,-2.275) 12(-2.85,-2.925) 13(-2.85,-3.575) 14(-2.85,-4.225) 15(2.85,-4.225) 16(2.85,-3.575) 17(2.85,-2.925) 18(2.85,-2.275) 19(2.85,-1.625) 20(2.85,-0.975) 21(2.85,-0.325) 22(2.85,0.325) 23(2.85,0.975) 24(2.85,1.625) 25(2.85,2.275) 26(2.85,2.925) 27(2.85,3.575) 28(2.85,4.225)
  rect 3.1x5.18 smd: 29(0,0)
  silkscreen extent -3.05,-4.9 1.6,4.92, body extent -3.21,-4.85 3.21,4.85, height 0.98
SM_RADIAL_10AMM [mm] "10 x 7.9mm:  Sanyo Oscon F8"
  rect 4.4x1.9 smd: 1(-4.35,0) 2(4.35,0)
  silkscreen extent -5.25,-5.25 5.25,5.25, body extent -5.25,-5.25 5.25,5.25, height 8
SMA [mm] "Molded Diode, 2-Leads, Body 4.3x2.6mm, IPC Medium Density, based on OnSemi component dimensions and land pattern"
  rect 2x2 smd: 1(-2,0) 2(2,0)
  silkscreen extent -3.66,-1.57 2.79,1.57, body extent -2.6,-1.3 2.6,1.3, height 2.42
sod-323 [mm] "NXP recommended land pattern"
  rect 0.6x0.6 smd paste-0.05: 1(-1.1,0) 2(1.1,0)
  silkscreen extent -2.06,-0.86 1.53,0.86, body extent -1.3,-0.67 1.3,0.68, height 1.1
SOD-323F [mm] "NXP recommended land pattern"
  rect 0.6x0.6 smd paste-0.05: 1(-1.1,0) 2(1.1,0)
  silkscreen extent -2.06,-0.86 1.53,0.86, body extent -1.35,-0.67 1.35,0.67, height 0.79
SW_CJS_1201A [mm] "Copal- Electronics"
  rect 1x1.6 smd paste+0 mask+0.05: 1(-1.75,-1.15) 2(0,1.15) 3(1.75,-1.15)
  silkscreen extent -3,-1.6 -2.7,-0.8, body extent -3,-1.55 3,1.55, height 2.51
TI_Stacked_SolderMask_Small [mil]
  rect 900x250 smd paste-125 mask-125: 0(0,0)

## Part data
C1: "CAP, AL, 180 µF, 50 V, +/- 20%, 0.019 ohm, SMD"
C2 C3 C4 C5: "CAP, CERM, 10 µF, 50 V, +/- 10%, X7R, 1210"
C6 C7 C8 C9 C10 C11: "CAP, CERM, 22 µF, 16 V, +/- 20%, X7R, 1210"
C12: "CAP, CERM, 1 µF, 25 V, +/- 10%, X7R, 0805"
C13 C14: "CAP, OS-CON, 330 µF, 16 V, +/- 20%, 0.016 ohm, 10x10.3 SMD"
C15: "CAP, CERM, 47pF, 50V, +/-5%, C0G/NP0, 0603"
C16: "CAP, CERM, 4.7 µF, 16 V, +/- 10%, X7R, 0805"
C17 C21: "CAP, CERM, 0.1uF, 100V, +/-10%, X7R, 0603"
C18 C19 C25: "CAP, CERM, 0.22 µF, 25 V, +/- 10%, X7R, 0603"
C20 C28 C29 C30: "CAP, CERM, 100pF, 100V, +/-5%, C0G/NP0, 0603"
C22 C27: "CAP, CERM, 0.022uF, 50V, +/-10%, X7R, 0603"
C23 C26: library part GRM1885C1H470JA01D, "CAP, CERM, 47pF, 50V, +/-5%, C0G/NP0, 0603"
C24: "CAP, CERM, 0.33 µF, 16 V, +/- 10%, X7R, 0603"
D1: "Diode, Schottky, 20 V, 5 A, SMA"
D2: "Diode, Schottky, 60 V, 3 A, SMA"
D3: "Diode, Schottky, 60 V, 1 A, SOD-323F"
D4 D5: "Diode, Ultrafast, 100V, 0.25A, SOD-323"
FID1 FID2 FID3: "Fiducial mark.  There is nothing to buy or mount."
H1 H2 H3 H4: "Machine Screw, Round, #4-40 x 1/4, Nylon, Philips panhead"
H5 H6 H7 H8: "Standoff, Hex, 0.5\"L #4-40 Nylon"
J1 J2 J3 J4: "Standard Banana Jack, Uninsulated, 15A"
L1: library part 74435580680, "INDUCTOR POWER 6.8UH 28.5A SMD"
LBL1: library part THT-14-423-10, "Thermal Transfer Printable Labels, 0.650\" W x 0.200\" H - 10,000 per roll"
Logo1: library part TI_Logo, "Texas Instrument Corporate Signature"
Logo2: library part Pb-Free
Logo3: library part FCC_disclaimer, "FCC_disclaimer"
LOGO4: library part IEC_HotSurface, "IEC 61010-1 Hot Surface Warning"
Q1 Q2 Q3 Q4: "MOSFET, N-CH, 60 V, 100 A, PG-TDSON-8"
Q5 Q6 Q7 Q8: "MOSFET, N-CH, 25 V, 33 A, PG-TDSON-8"
R1: library part KRL6432E-M-R004-F-T1, "RES 0.004 OHM 3W 1% 2512 WIDE"
R2 R3 R4 R5 R12 R15 R17 R24 R25 R26 R27: "RES, 0 ohm, 5%, 0.1W, 0603"
R6 R8: "RES, 100 ohm, 1%, 0.1W, 0603"
R7: "RES, 0.004, 1%, 6 W, 4320_WIDE"
R9 R11: "RES, 10.0 ohm, 1%, 0.1W, 0603"
R10 R23: "RES, 10.0k ohm, 1%, 0.1W, 0603"
R13: "RES, 249k ohm, 1%, 0.1W, 0603"
R14: "RES, 280k ohm, 1%, 0.1W, 0603"
R16 R21: library part RC0603FR-07100RL, "RES, 100 ohm, 1%, 0.1W, 0603"
R18: "RES, 59.0k ohm, 1%, 0.1W, 0603"
R19: "RES, 93.1 k, 1%, 0.1 W, 0603"
R20: "RES, 100 k, 1%, 0.1 W, 0603"
R22: "RES, 20.0k ohm, 1%, 0.1W, 0603"
S1 S2 S3: "Slide SW, SPDT 0.1A 50VDC"
TP1 TP3: "Test Point, Compact, Red, TH"
TP2 TP4: "Test Point, Compact, Black, TH"
TP5: "Test Point, Compact, White, TH"
TP6 TP7: library part 5007, "Test Point, Compact, White, TH"
U1: "42V Wide VIN 4-Switch Synchronous Buck-Boost Controller, PWP0028F"
ZZ1: library part AssemblyNoteLabel
ZZ2 ZZ3 ZZ4 ZZ5 ZZ6 ZZ7 ZZ8: library part AssemblyNote

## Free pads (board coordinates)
  rect 50.01x50.01 smd far side rot 45 paste-50.01: 0(83,416) 0(83,491) 0(83,566) 0(83,641) 0(83,716) 0(83,791) 0(83,866) 0(83,941) 0(83,1016) 0(83,1091) 0(83,1166) 0(83,1241) 0(83,1316) 0(83,1391) 0(83,1466) 0(83,1541) 0(83,1616) 0(83,1691) 0(83,1766) 0(83,1841) 0(83,1916) 0(83,1991) 0(83,2066) 0(83,2141) 0(83,2216) 0(83,2291) 0(83,2366) 0(83,2441) 0(83,2516) 0(83,2591) 0(83,2666) 0(83,2741) 0(83,2816) 0(83,2891) 0(83,2966) 0(83,3041) 0(83,3116) 0(83,3191) 0(83,3266) 0(158,416) 0(158,491) 0(158,566) 0(158,641) 0(158,716) 0(158,791) 0(158,866) 0(158,941) 0(158,1016) 0(158,1091) 0(158,1166) 0(158,1241) 0(158,1316) 0(158,1391) 0(158,1466) 0(158,1541) 0(158,1616) 0(158,1691) 0(158,1766) 0(158,1841) 0(158,1916) 0(158,1991) 0(158,2066) 0(158,2141) 0(158,2216) 0(158,2291) 0(158,2366) 0(158,2441) 0(158,2516) 0(158,2591) 0(158,2666) 0(158,2741) 0(158,2816) 0(158,2891) 0(158,2966) 0(158,3041) 0(158,3116) 0(158,3191) 0(233,416) 0(233,491) 0(233,566) 0(233,641) 0(233,716) 0(233,791) 0(233,866) 0(233,941) 0(233,1016) 0(233,1091) 0(233,1166) 0(233,1241) 0(233,1316) 0(233,1391) 0(233,1466) 0(233,1541) 0(233,1616) 0(233,1691) 0(233,1766) 0(233,1841) 0(233,1916) 0(233,1991) 0(233,2066) 0(233,2141) 0(233,2216) 0(233,2291) 0(233,2366) 0(233,2441) 0(233,2516) 0(233,2591) 0(233,2666) 0(233,2741) 0(233,2816) 0(233,2891) 0(233,2966) 0(233,3041) 0(233,3116) 0(233,3191) 0(308,416) 0(308,491) 0(308,566) 0(308,641) 0(308,716) 0(308,791) 0(308,866) 0(308,941) 0(308,1016) 0(308,1091) 0(308,1166) 0(308,1241) 0(308,1316) 0(308,1391) 0(308,1466) 0(308,1541) 0(308,1616) 0(308,1691) 0(308,1766) 0(308,1841) 0(308,1916) 0(308,1991) 0(308,2066) 0(308,2141) 0(308,2216) 0(308,2291) 0(308,2366) 0(308,2441) 0(308,2516) 0(308,2591) 0(308,2666) 0(308,2741) 0(308,2816) 0(308,2891) 0(308,2966) 0(308,3041) 0(308,3116) 0(308,3191) 0(308,3266) 0(383,341) 0(383,416) 0(383,491) 0(383,566) 0(383,641) 0(383,716) 0(383,791) 0(383,866) 0(383,941) 0(383,1016) 0(383,2591) 0(383,2666) 0(383,2741) 0(383,2816) 0(383,2891) 0(383,2966) 0(383,3041) 0(383,3116) 0(383,3191) 0(383,3266) 0(383,3341) 0(383,3566) 0(458,116) 0(458,191) 0(458,266) 0(458,341) 0(458,416) 0(458,491) 0(458,566) 0(458,641) 0(458,716) 0(458,791) 0(458,866) 0(458,941) 0(458,1016) 0(458,2591) 0(458,2666) 0(458,2741) 0(458,2816) 0(458,2891) 0(458,2966) 0(458,3041) 0(458,3116) 0(458,3191) 0(458,3266) 0(458,3341) 0(458,3416) 0(458,3491) 0(458,3566) 0(533,116) 0(533,191) 0(533,266) 0(533,341) 0(533,416) 0(533,491) 0(533,566) 0(533,641) 0(533,716) 0(533,791) 0(533,866) 0(533,941) 0(533,1016) 0(533,2591) 0(533,2666) 0(533,2741) 0(533,2816) 0(533,2891) 0(533,2966) 0(533,3041) 0(533,3116) 0(533,3191) 0(533,3266) 0(533,3341) 0(533,3416) 0(533,3491) 0(533,3566) 0(608,416) 0(608,491) 0(608,566) 0(608,641) 0(608,716) 0(608,791) 0(608,2891) 0(608,2966) 0(608,3041) 0(608,3116) 0(608,3191) 0(608,3491) 0(608,3566) 0(683,416) 0(683,491) 0(683,566) 0(683,641) 0(683,716) 0(683,2966) 0(683,3041) 0(683,3116) 0(683,3191) 0(683,3491) 0(683,3566) 0(758,266) 0(758,341) 0(758,416) 0(758,491) 0(758,566) 0(758,641) 0(758,3041) 0(758,3116) 0(758,3191) 0(758,3266) 0(758,3341) 0(758,3416) 0(758,3491) 0(758,3566) 0(833,266) 0(833,341) 0(833,416) 0(833,491) 0(833,566) 0(833,3116) 0(833,3191) 0(833,3266) 0(833,3341) 0(833,3416) 0(833,3491) 0(833,3566) 0(908,266) 0(908,341) 0(908,416) 0(908,491) 0(908,3191) 0(908,3266) 0(908,3341) 0(908,3416) 0(908,3491) 0(908,3566) 0(983,266) 0(983,341) 0(983,416) 0(983,3266) 0(983,3341) 0(983,3416) 0(983,3491) 0(983,3566) 0(1058,266) 0(1058,341) 0(1058,3341) 0(1058,3416) 0(1058,3491) 0(1058,3566) 0(1133,266) 0(1133,3341) 0(1133,3416) 0(1133,3491) 0(1133,3566) 0(1208,266) 0(1208,3341) 0(1208,3416) 0(1208,3491) 0(1208,3566) 0(1283,266) 0(1283,3341) 0(1283,3416) 0(1283,3491) 0(1283,3566) 0(1358,116) 0(1358,191) 0(1358,266) 0(1358,3341) 0(1358,3416) 0(1358,3491) 0(1358,3566) 0(1433,116) 0(1433,191) 0(1433,266) 0(1433,3341) 0(1433,3416) 0(1433,3491) 0(1433,3566) 0(1508,116) 0(1508,191) 0(1508,266) 0(1508,3341) 0(1508,3416) 0(1508,3491) 0(1508,3566) 0(1583,116) 0(1583,191) 0(1583,266) 0(1583,3341) 0(1583,3416) 0(1583,3491) 0(1583,3566) 0(1658,116) 0(1658,191) 0(1658,266) 0(1658,3341) 0(1658,3416) 0(1658,3491) 0(1658,3566) 0(1733,116) 0(1733,191) 0(1733,266) 0(1733,3341) 0(1733,3416) 0(1733,3491) 0(1733,3566) 0(1808,116) 0(1808,191) 0(1808,266) 0(1808,3341) 0(1808,3416) 0(1808,3491) 0(1808,3566) 0(1883,116) 0(1883,191) 0(1883,266) 0(1883,3341) 0(1883,3416) 0(1883,3491) 0(1883,3566) 0(1958,116) 0(1958,191) 0(1958,266) 0(1958,3341) 0(1958,3416) 0(1958,3491) 0(1958,3566) 0(2033,116) 0(2033,191) 0(2033,266) 0(2033,3341) 0(2033,3416) 0(2033,3491) 0(2033,3566) 0(2108,266) 0(2108,3341) 0(2108,3416) 0(2108,3491) 0(2108,3566) 0(2183,266) 0(2183,3341) 0(2183,3416) 0(2183,3491) 0(2183,3566) 0(2258,266) 0(2258,3341) 0(2258,3416) 0(2258,3491) 0(2258,3566) 0(2333,266) 0(2333,3341) 0(2333,3416) 0(2333,3491) 0(2333,3566) 0(2408,266) 0(2408,3341) 0(2408,3416) 0(2408,3491) 0(2408,3566) 0(2483,266) 0(2483,3341) 0(2483,3416) 0(2483,3491) 0(2483,3566) 0(2558,266) 0(2558,3341) 0(2558,3416) 0(2558,3491) 0(2558,3566) 0(2633,116) 0(2633,191) 0(2633,266) 0(2633,3341) 0(2633,3416) 0(2633,3491) 0(2633,3566) 0(2708,116) 0(2708,191) 0(2708,266) 0(2708,3341) 0(2708,3416) 0(2708,3491) 0(2708,3566) 0(2783,116) 0(2783,191) 0(2783,266) 0(2783,3341) 0(2783,3416) 0(2783,3491) 0(2783,3566) 0(2858,116) 0(2858,191) 0(2858,266) 0(2858,3341) 0(2858,3416) 0(2858,3491) 0(2858,3566) 0(2933,116) 0(2933,191) 0(2933,266) 0(2933,3341) 0(2933,3416) 0(2933,3491) 0(2933,3566) 0(3008,116) 0(3008,191) 0(3008,266) 0(3008,3341) 0(3008,3416) 0(3008,3491) 0(3008,3566) 0(3083,116) 0(3083,191) 0(3083,266) 0(3083,3341) 0(3083,3416) 0(3083,3491) 0(3083,3566) 0(3158,116) 0(3158,191) 0(3158,3341) 0(3158,3416) 0(3158,3491) 0(3158,3566) 0(3233,116) 0(3233,191) 0(3233,3341) 0(3233,3416) 0(3233,3491) 0(3233,3566) 0(3308,116) 0(3308,191) 0(3308,266) 0(3308,3341) 0(3308,3416) 0(3308,3491) 0(3308,3566) 0(3383,116) 0(3383,191) 0(3383,266) 0(3383,3341) 0(3383,3416) 0(3383,3491) 0(3383,3566)
  rect 50.01x50.01 smd rot 45 paste-50.01: 0(83,416) 0(83,491) 0(83,566) 0(83,641) 0(83,716) 0(83,791) 0(83,866) 0(83,941) 0(83,1016) 0(83,1091) 0(83,1166) 0(83,1241) 0(83,1316) 0(83,1391) 0(83,1466) 0(83,1541) 0(83,1616) 0(83,1691) 0(83,1766) 0(83,1841) 0(83,1916) 0(83,1991) 0(83,2066) 0(83,2141) 0(83,2216) 0(83,2291) 0(83,2366) 0(83,2441) 0(83,2516) 0(83,2591) 0(83,2666) 0(83,2741) 0(83,2816) 0(83,2891) 0(83,2966) 0(83,3041) 0(83,3116) 0(83,3191) 0(83,3266) 0(158,416) 0(158,491) 0(158,566) 0(158,641) 0(158,716) 0(158,791) 0(158,866) 0(158,941) 0(158,1016) 0(158,1091) 0(158,1166) 0(158,1241) 0(158,1316) 0(158,1391) 0(158,1466) 0(158,1541) 0(158,1616) 0(158,1691) 0(158,1766) 0(158,1841) 0(158,1916) 0(158,1991) 0(158,2066) 0(158,2141) 0(158,2216) 0(158,2291) 0(158,2366) 0(158,2441) 0(158,2516) 0(158,2591) 0(158,2666) 0(158,2741) 0(158,2816) 0(158,2891) 0(158,2966) 0(158,3041) 0(158,3116) 0(158,3191) 0(233,416) 0(233,491) 0(233,566) 0(233,641) 0(233,716) 0(233,791) 0(233,866) 0(233,941) 0(233,1016) 0(233,1091) 0(233,1166) 0(233,1241) 0(233,1316) 0(233,1391) 0(233,1466) 0(233,1541) 0(233,1616) 0(233,1691) 0(233,1766) 0(233,1841) 0(233,1916) 0(233,1991) 0(233,2066) 0(233,2141) 0(233,2216) 0(233,2291) 0(233,2366) 0(233,2441) 0(233,2516) 0(233,2591) 0(233,2666) 0(233,2741) 0(233,2816) 0(233,2891) 0(233,2966) 0(233,3041) 0(233,3116) 0(233,3191) 0(308,416) 0(308,491) 0(308,566) 0(308,641) 0(308,716) 0(308,791) 0(308,866) 0(308,941) 0(308,1016) 0(308,1091) 0(308,1166) 0(308,1241) 0(308,1316) 0(308,1391) 0(308,1466) 0(308,1541) 0(308,1616) 0(308,1691) 0(308,1766) 0(308,1841) 0(308,1916) 0(308,1991) 0(308,2066) 0(308,2141) 0(308,2216) 0(308,2291) 0(308,2366) 0(308,2441) 0(308,2516) 0(308,2591) 0(308,2666) 0(308,2741) 0(308,2816) 0(308,2891) 0(308,2966) 0(308,3041) 0(308,3116) 0(308,3191) 0(308,3266) 0(383,341) 0(383,416) 0(383,491) 0(383,566) 0(383,641) 0(383,716) 0(383,791) 0(383,866) 0(383,941) 0(383,1016) 0(383,2591) 0(383,2666) 0(383,2741) 0(383,2816) 0(383,2891) 0(383,2966) 0(383,3041) 0(383,3116) 0(383,3191) 0(383,3266) 0(383,3341) 0(383,3566) 0(458,116) 0(458,191) 0(458,266) 0(458,341) 0(458,416) 0(458,491) 0(458,566) 0(458,641) 0(458,716) 0(458,791) 0(458,866) 0(458,941) 0(458,1016) 0(458,2591) 0(458,2666) 0(458,2741) 0(458,2816) 0(458,2891) 0(458,2966) 0(458,3041) 0(458,3116) 0(458,3191) 0(458,3266) 0(458,3341) 0(458,3416) 0(458,3491) 0(458,3566) 0(533,116) 0(533,191) 0(533,416) 0(533,491) 0(533,566) 0(533,641) 0(533,716) 0(533,791) 0(533,866) 0(533,941) 0(533,1016) 0(533,2591) 0(533,2666) 0(533,2741) 0(533,2816) 0(533,2891) 0(533,2966) 0(533,3041) 0(533,3116) 0(533,3191) 0(533,3266) 0(533,3416) 0(533,3491) 0(533,3566) 0(608,116) 0(608,491) 0(608,566) 0(608,641) 0(608,716) 0(608,791) 0(608,2891) 0(608,2966) 0(608,3041) 0(608,3116) 0(608,3191) 0(608,3491) 0(608,3566) 0(683,116) 0(683,416) 0(683,491) 0(683,566) 0(683,641) 0(683,716) 0(683,2966) 0(683,3041) 0(683,3116) 0(683,3191) 0(683,3491) 0(683,3566) 0(758,116) 0(758,191) 0(758,341) 0(758,416) 0(758,491) 0(758,566) 0(758,641) 0(758,3041) 0(758,3116) 0(758,3191) 0(758,3266) 0(758,3416) 0(758,3491) 0(758,3566) 0(833,116) 0(833,191) 0(833,266) 0(833,341) 0(833,416) 0(833,491) 0(833,566) 0(833,3116) 0(833,3191) 0(833,3266) 0(833,3341) 0(833,3416) 0(833,3491) 0(833,3566) 0(908,116) 0(908,191) 0(908,266) 0(908,341) 0(908,416) 0(908,491) 0(908,3191) 0(908,3266) 0(908,3341) 0(908,3416) 0(908,3491) 0(908,3566) 0(983,116) 0(983,191) 0(983,266) 0(983,341) 0(983,416) 0(983,3266) 0(983,3341) 0(983,3416) 0(983,3491) 0(983,3566) 0(1058,341) 0(1808,191) 0(1808,266) 0(1883,191) 0(1883,266) 0(1958,191) 0(1958,266) 0(2033,191) 0(2033,266) 0(2033,3491) 0(2033,3566) 0(2108,266) 0(2108,3491) 0(2108,3566) 0(2110,190) 0(2183,266) 0(2183,3491) 0(2183,3566) 0(2185,190) 0(2255,190) 0(2258,266) 0(2258,3491) 0(2258,3566) 0(2330,190) 0(2333,266) 0(2333,3491) 0(2333,3566) 0(2408,266) 0(2408,3491) 0(2408,3566) 0(2410,190) 0(2483,266) 0(2483,3491) 0(2483,3566) 0(2487,189) 0(2558,266) 0(2558,3491) 0(2558,3566) 0(2562,189) 0(2632,189) 0(2633,266) 0(2633,3341) 0(2633,3416) 0(2633,3491) 0(2633,3566) 0(2707,189) 0(2708,266) 0(2708,3341) 0(2708,3416) 0(2708,3491) 0(2708,3566) 0(2783,116) 0(2783,191) 0(2783,266) 0(2783,3341) 0(2783,3416) 0(2783,3491) 0(2783,3566) 0(2858,116) 0(2858,191) 0(2858,266) 0(2858,3341) 0(2858,3416) 0(2858,3491) 0(2858,3566) 0(2933,116) 0(2933,191) 0(2933,266) 0(2933,3341) 0(2933,3416) 0(2933,3491) 0(2933,3566) 0(3008,116) 0(3008,191) 0(3008,266) 0(3008,3341) 0(3008,3416) 0(3008,3491) 0(3008,3566) 0(3083,116) 0(3083,191) 0(3083,266) 0(3083,3341) 0(3083,3416) 0(3083,3491) 0(3083,3566) 0(3158,116) 0(3158,191) 0(3158,3341) 0(3158,3416) 0(3158,3491) 0(3158,3566) 0(3233,116) 0(3233,3341) 0(3233,3416) 0(3233,3491) 0(3233,3566) 0(3308,116) 0(3308,191) 0(3308,3341) 0(3308,3416) 0(3308,3491) 0(3308,3566) 0(3383,116) 0(3383,191) 0(3383,266) 0(3383,3341) 0(3383,3416) 0(3383,3491) 0(3383,3566)

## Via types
v1: diameter 24, hole 10, Top Layer to Bottom Layer, tented both sides, 272 vias
v2: diameter 24, hole 10, Top Layer to Bottom Layer, 97 vias
v3: diameter 24, hole 14, Top Layer to Bottom Layer, 19 vias
v4: diameter 15.75, hole 7.87, Top Layer to Bottom Layer, 15 vias
v5: diameter 38, hole 24, Top Layer to Bottom Layer, 2 vias
v6: diameter 38, hole 24, Top Layer to Bottom Layer, tented both sides, 1 vias

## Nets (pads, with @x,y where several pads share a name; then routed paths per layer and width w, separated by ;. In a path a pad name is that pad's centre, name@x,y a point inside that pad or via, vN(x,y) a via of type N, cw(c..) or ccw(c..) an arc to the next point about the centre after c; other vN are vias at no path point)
BIAS: C25.1 R12.2 TP6.1 U1.24 | length 1326.9
  Top Layer w12: v2@1895.69,1855.69 C25.1@1958.62,1855.69
  MidLayer2 w12: v2(1895,1855) 2015,1735 2015,1705 2165,1555 v2(2410,1555)
  MidLayer3 w12: v2(1895,1855) 2085,2045 TP6.1@2085,2135 TP6.1@2085,2160
  Bottom Layer w12: v2@1895.39,1854.61 U1.24@1972.8,1854.61 ; R12.2@2407.44,1410 2407.44,1552.44 v2(2410,1555)
CS: C15.1 R6.1 U1.16 | length 256.8
  Bottom Layer w12: C15.1@1845,1547.44 1845,1585 1909.88,1649.88 U1.16@1972.8,1649.88 ; R6.1@1847.44,1490.44 C15.1@1847.44,1555
CSG: C15.2 R8.1 U1.15 | length 176.2
  Bottom Layer w12: R8.1@1905,1507.56 1905,1610 1919.29,1624.29 U1.15@1972.8,1624.29
DITHER: C27.1 S3.2 U1.5 | length 926.7
  MidLayer3 w10: v2(2430,2013.43) 2488.43,1955 2870,1955 v2(2895,1980)
  Bottom Layer w10: U1.5@2197.2,1854.61 2315.35,1854.61 2331.38,1870.63 2331.38,1937.01 2407.8,2013.43 v2(2430,2013.43) C27.1@2474.64,2013.43 ; v2(2895,1980) S3.2@2940,1980
EN: C23.1 R13.1 R18.2 S2.2 U1.1 | length 908.9
  MidLayer3 w10: v2(2255,1960.63) 2359.37,2065 v2(2425,2065) 2755,2065 v2(2805,2115)
  Bottom Layer w10: U1.1@2197.2,1956.97 2251.34,1956.97 v2(2255,1960.63) ; v2(2425,2065) R18.2@2477.44,2065 C23.1@2477.44,2115 2477.44,2162.56 2475,2165 R13.1@2475,2192.44 ; v2(2805,2115) S2.2@2805,2169.72
FB: R14.1 R22.2 U1.11 | length 280.2
  Bottom Layer w10: U1.11@2197.2,1701.06 2384.57,1701.06 2395,1690.63 R22.2@2422.38,1690.63 R22.2@2422.38,1690.63 R14.1@2422.44,1640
